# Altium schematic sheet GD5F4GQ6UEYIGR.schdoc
size 127 x 101 mm
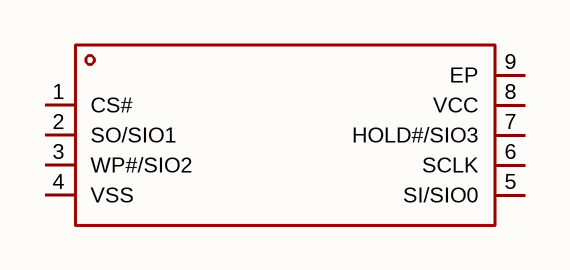
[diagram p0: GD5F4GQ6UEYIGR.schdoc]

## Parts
U?  gd5f4gq6ueyigr  [WSON-8_L8.0-W6.0-P1.27-TL-EP-1]  (value not drawn)

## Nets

Not connected (* = marked no-connect by the designer): U? 1(CS#) 2(SO/SIO1) 3(WP#/SIO2) 4(VSS) 5(SI/SIO0) 6(SCLK) 7(HOLD#/SIO3) 8(VCC) 9(EP)

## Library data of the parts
U? = gd5f4gq6ueyigr: 存储容量:4Gbit;时钟频率(fc):104MHz;工作电压:2.7V~3.6V;; Manufacturer: GigaDevice(兆易创新); AddInBom: yes; ModelId: 9b0b95cb42c44ddaa75bcc393c15d437; ModelTransform: 314.96,236.22,0,0,0,0,0,0,0; Memory Size: 4Gbit; Interface: SPI; Clock Frequency: 104MHz; Page Program time (TPP): 300us; Block Erase Time(tBE): 3ms; Standby Supply Current: 50uA; Program / Erase Cycles: 10万次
